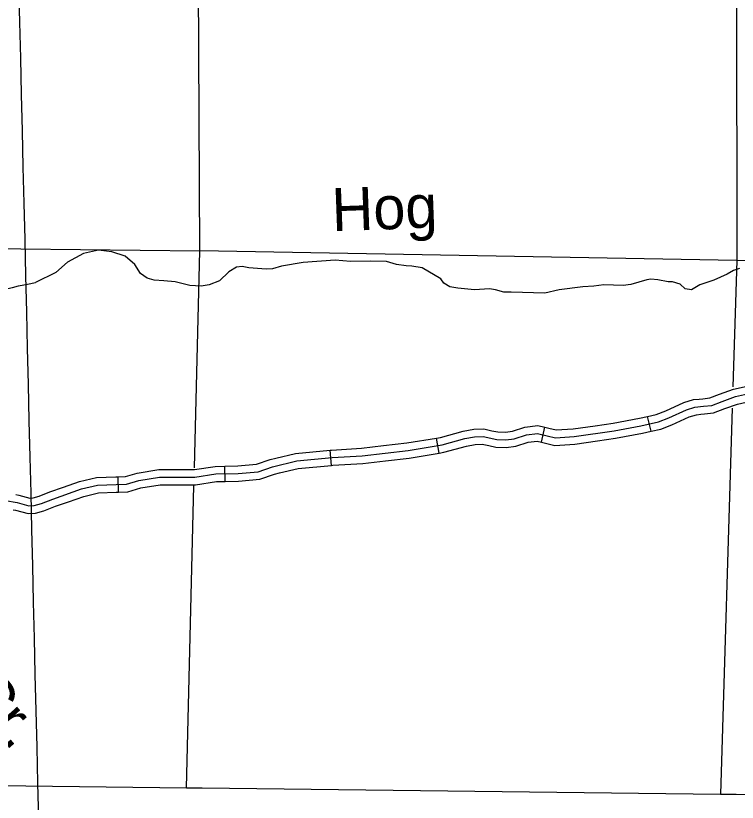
# Model space of a CAD drawing. Extents: x -19 to 366, y -4 to 359.
# Drawn here: x 135.055 to 136.395, y 192.02 to 193.481 of the extents above; entities that cross this region are included whole.
import ezdxf

# ---------------------------------------------------------------- set-up
doc = ezdxf.new("R2010")
doc.units = 0
for name, color, linetype in [('R_Alt Surface', 7, 'Continuous'), ('R_Axis Annot', 7, 'Continuous'), ('R_Temp Easement', 7, 'Continuous'), ('Sheet Fence', 7, 'Continuous'), ('T_Indications', 7, 'Continuous')]:
    doc.layers.add(name, color=color, linetype=linetype)

msp = doc.modelspace()

# ---------------------------------------------------------------- linework, layer by layer
at = {"layer": 'R_Alt Surface'}
msp.add_lwpolyline([(133.9509, 192.0638), (134.386, 192.0586), (134.4263, 192.0586), (135.372, 192.0471), (135.4008, 192.0467), (136.3634, 192.0352), (136.3927, 192.035), (137.3674, 192.0278), (137.3965, 192.0275), (137.874, 192.0242)], dxfattribs=at)
at = {"layer": 'R_Axis Annot'}
for points in [[(136.3928, 194.0289), (136.3939, 193.0262)], [(135.3964, 193.0443), (135.3933, 193.6647)], [(134.3989, 193.0554), (135.3964, 193.0443)], [(135.3865, 192.6409), (135.3964, 193.0443)], [(136.3939, 193.0262), (135.3964, 193.0443)], [(136.3939, 193.0262), (136.3867, 192.7915)], [(136.9875, 193.0242), (136.3939, 193.0262)], [(136.3855, 192.7522), (136.3634, 192.0352)], [(135.372, 192.0471), (135.3857, 192.6076)]]:
    msp.add_lwpolyline(points, dxfattribs=at)
at = {"layer": 'R_Temp Easement'}
for points in [[(135.475, 193.0154), (135.4649, 193.0139), (135.4502, 193.005), (135.4329, 192.9883), (135.4137, 192.9813), (135.399, 192.9787), (135.3779, 192.98), (135.351, 192.9864), (135.3299, 192.9883), (135.312, 192.9896), (135.2986, 192.9934), (135.2865, 193.0024), (135.2756, 193.019), (135.2577, 193.0344), (135.2334, 193.0421), (135.2084, 193.0453), (135.1803, 193.0395), (135.1509, 193.0229), (135.1291, 193.0037), (135.0916, 192.9857)], [(135.7798, 193.0162), (135.7616, 193.0191), (135.7434, 193.0244), (135.7139, 193.025), (135.6765, 193.0245), (135.6478, 193.027), (135.5884, 193.0226), (135.548, 193.016), (135.5314, 193.011), (135.5196, 193.0099), (135.4879, 193.0124), (135.475, 193.0154)], [(136.3991, 193.0117), (136.3878, 193.0075), (136.3761, 193.0006), (136.3512, 192.9895), (136.3252, 192.9811), (136.3097, 192.9719), (136.298, 192.9737), (136.2885, 192.9824), (136.2745, 192.9869), (136.2662, 192.9865), (136.2472, 192.9902), (136.2344, 192.9917), (136.2268, 192.9905), (136.197, 192.9817), (136.183, 192.9798), (136.1471, 192.9808), (136.1282, 192.9784), (136.1078, 192.9772), (136.0639, 192.9717), (136.0375, 192.9659), (135.9751, 192.9676), (135.9611, 192.9672), (135.9456, 192.9716), (135.9346, 192.9735), (135.907, 192.9715), (135.8756, 192.9748), (135.8608, 192.9774), (135.8499, 192.9842), (135.8441, 192.9925), (135.8097, 193.0129), (135.7904, 193.0158), (135.7798, 193.0162)], [(134.6272, 192.9315), (134.6473, 192.9359), (134.6638, 192.9337), (134.704, 192.933), (134.7174, 192.9356), (134.7392, 192.9407), (134.7654, 192.9445), (134.7967, 192.9474), (134.8163, 192.9498), (134.8416, 192.9522), (134.868, 192.9559), (134.8957, 192.9593), (134.9304, 192.9614), (134.9698, 192.9638), (134.9974, 192.9667), (135.0132, 192.9688), (135.0484, 192.976), (135.06, 192.9791), (135.0764, 192.9821), (135.0916, 192.9857)]]:
    msp.add_lwpolyline(points, dxfattribs=at)
at = {"layer": 'Sheet Fence'}
for points in [[(139.4406, 1.5315), (139.2511, 10.1473), (139.0608, 18.7633), (138.8699, 27.3793), (138.6784, 35.9956), (138.4861, 44.6119), (138.2932, 53.2285), (138.0997, 61.8451), (137.9055, 70.4619), (137.7106, 79.0789), (137.5151, 87.6959), (137.319, 96.3132), (137.1221, 104.9306), (136.9247, 113.5481), (136.7265, 122.1658), (136.5278, 130.7836), (136.3283, 139.4016), (136.1282, 148.0197), (135.9275, 156.6379), (135.7261, 165.2564), (135.5241, 173.8749), (135.3214, 182.4936), (135.1181, 191.1125), (134.9141, 199.7315), (134.7095, 208.3506), (134.5043, 216.9699), (134.2984, 225.5894), (134.0919, 234.209), (133.8847, 242.8288), (133.6769, 251.4487), (133.4685, 260.0687), (133.2594, 268.6889), (133.0497, 277.3093), (132.8393, 285.9298), (132.6283, 294.5504), (132.4167, 303.1713), (132.2044, 311.7922), (131.9916, 320.4133), (131.778, 329.0346), (131.5639, 337.656), (131.3491, 346.2776)], [(0, 189.5162), (7.1121, 189.5206), (14.2243, 189.5339), (21.3364, 189.556), (28.4484, 189.5869), (35.5605, 189.6267), (42.6725, 189.6754), (49.7844, 189.7329), (56.8962, 189.7992), (64.0079, 189.8744), (71.1196, 189.9584), (78.2311, 190.0512), (85.3425, 190.1529), (92.4538, 190.2635), (99.5649, 190.3829), (106.6759, 190.5111), (113.7867, 190.6482), (120.8974, 190.7941), (128.0078, 190.9489), (135.1181, 191.1125), (142.2282, 191.2849), (149.338, 191.4662), (156.4476, 191.6563), (163.5569, 191.8553), (170.666, 192.0631), (177.7749, 192.2798), (184.8835, 192.5053), (191.9917, 192.7396), (199.0997, 192.9828), (206.2074, 193.2348), (213.3147, 193.4956), (220.4218, 193.7653), (227.5285, 194.0438), (234.6348, 194.3312), (241.7408, 194.6274), (248.8464, 194.9324), (255.9516, 195.2463), (263.0564, 195.569), (270.1608, 195.9005), (277.2648, 196.2409), (284.3683, 196.5901), (291.4715, 196.9481), (298.5741, 197.315), (305.6763, 197.6907), (312.7781, 198.0753), (319.8793, 198.4686), (326.9801, 198.8708), (334.0804, 199.2818), (341.1801, 199.7017)]]:
    msp.add_spline(points, degree=3, dxfattribs=at)
at = {"layer": 'T_Indications'}
for p, q in [((136.2347, 192.709), (136.2283, 192.7367)), ((136.031, 192.6888), (136.0374, 192.7165)), ((135.8408, 192.6685), (135.8363, 192.6965)), ((135.6413, 192.6458), (135.6386, 192.674)), ((135.4435, 192.6159), (135.4429, 192.6443)), ((135.2455, 192.5961), (135.2449, 192.6245))]:
    msp.add_line(p, q, dxfattribs=at)
for points in [[(136.3242, 192.7689), (136.3308, 192.7696), (136.3439, 192.771), (136.3615, 192.778), (136.3875, 192.7871), (136.4188, 192.794)], [(136.3161, 192.7538), (136.3323, 192.7555), (136.3473, 192.7571), (136.3665, 192.7646), (136.3914, 192.7734), (136.4305, 192.7821)], [(136.2283, 192.7367), (136.2441, 192.7404), (136.2623, 192.7473), (136.2953, 192.7626), (136.3134, 192.7678), (136.3242, 192.7689)], [(136.3271, 192.7407), (136.3339, 192.7413), (136.3508, 192.7432), (136.3714, 192.7513), (136.3953, 192.7597), (136.425, 192.7663)], [(135.0359, 192.5802), (135.0576, 192.5765), (135.0792, 192.5706), (135.0892, 192.5711), (135.1025, 192.5748), (135.1233, 192.5831), (135.177, 192.6019), (135.2065, 192.6089), (135.2411, 192.6102), (135.2606, 192.6106), (135.2835, 192.6177), (135.3218, 192.6239), (135.3534, 192.6239), (135.3875, 192.6239), (135.4262, 192.6298), (135.4678, 192.6306), (135.5048, 192.6339), (135.5315, 192.6431), (135.5768, 192.6539), (135.6425, 192.6601), (135.6983, 192.6635), (135.7832, 192.6735), (135.8468, 192.6839), (135.8888, 192.6955), (135.9067, 192.6989), (135.9225, 192.6993), (135.9479, 192.6939), (135.965, 192.693), (135.9804, 192.6951), (136.0033, 192.7026), (136.0236, 192.7051), (136.0415, 192.7009), (136.0573, 192.6972), (136.0915, 192.6993), (136.1663, 192.7101), (136.2159, 192.7193), (136.2483, 192.7268), (136.2679, 192.7342), (136.3003, 192.7492), (136.3161, 192.7538)], [(136.2347, 192.709), (136.2525, 192.7131), (136.2734, 192.7211), (136.3053, 192.7359), (136.3188, 192.7398), (136.3271, 192.7407)], [(136.131, 192.7193), (136.164, 192.7241), (136.213, 192.7332), (136.2283, 192.7367)], [(135.8363, 192.6965), (135.8438, 192.6978), (135.8856, 192.7094), (135.9052, 192.713), (135.9239, 192.7135), (135.9392, 192.7102)], [(135.9392, 192.7102), (135.9498, 192.708), (135.9644, 192.7073), (135.9772, 192.709), (136.0001, 192.7165), (136.0244, 192.7195), (136.0374, 192.7165)], [(136.0374, 192.7165), (136.0448, 192.7148), (136.0586, 192.7115), (136.09, 192.7134), (136.131, 192.7193)], [(136.1351, 192.6912), (136.1686, 192.6961), (136.2187, 192.7053), (136.2347, 192.709)], [(135.6386, 192.674), (135.6414, 192.6743), (135.697, 192.6776), (135.7379, 192.6824)], [(135.7379, 192.6824), (135.7812, 192.6875), (135.8363, 192.6965)], [(135.8408, 192.6685), (135.8499, 192.67), (135.892, 192.6817), (135.9082, 192.6847), (135.9212, 192.685), (135.9333, 192.6825)], [(135.9333, 192.6825), (135.9461, 192.6797), (135.9656, 192.6788), (135.9836, 192.6812), (136.0064, 192.6887), (136.0229, 192.6907), (136.031, 192.6888)], [(136.031, 192.6888), (136.0383, 192.6871), (136.0561, 192.6829), (136.0929, 192.6851), (136.1351, 192.6912)], [(135.538, 192.6592), (135.5745, 192.6679), (135.6386, 192.674)], [(135.7412, 192.6542), (135.7851, 192.6594), (135.8408, 192.6685)], [(135.4429, 192.6443), (135.467, 192.6448), (135.5018, 192.6479), (135.5275, 192.6567), (135.538, 192.6592)], [(135.6413, 192.6458), (135.6436, 192.646), (135.6995, 192.6493), (135.7412, 192.6542)], [(135.3437, 192.6381), (135.3534, 192.6381), (135.3864, 192.6381), (135.425, 192.6439), (135.4429, 192.6443)], [(135.5446, 192.6316), (135.5791, 192.6399), (135.6413, 192.6458)], [(135.1432, 192.6051), (135.173, 192.6155), (135.2046, 192.6231), (135.2407, 192.6244), (135.2449, 192.6245)], [(135.2449, 192.6245), (135.2583, 192.6248), (135.2802, 192.6315), (135.3206, 192.6381), (135.3437, 192.6381)], [(135.4435, 192.6159), (135.4686, 192.6164), (135.5078, 192.6199), (135.5354, 192.6294), (135.5446, 192.6316)], [(135.2455, 192.5961), (135.2629, 192.5965), (135.2868, 192.6038), (135.3229, 192.6097), (135.3437, 192.6097)], [(135.3437, 192.6097), (135.3534, 192.6097), (135.3886, 192.6097), (135.4274, 192.6156), (135.4435, 192.6159)], [(135.0547, 192.5914), (135.0606, 192.5904), (135.0808, 192.5849), (135.087, 192.5852), (135.0979, 192.5883), (135.1183, 192.5964), (135.1432, 192.6051)], [(135.1525, 192.5783), (135.181, 192.5882), (135.2085, 192.5948), (135.2415, 192.596), (135.2455, 192.5961)], [(135.0498, 192.5634), (135.0545, 192.5626), (135.0776, 192.5564), (135.0915, 192.5569), (135.1071, 192.5613), (135.1283, 192.5698), (135.1525, 192.5783)]]:
    msp.add_lwpolyline(points, dxfattribs=at)

# ---------------------------------------------------------------- texts
at = {"layer": 'R_Temp Easement'}
for s, rotation, p in [('Hog', 2.0404, (135.6428, 193.0805)), ('Cr.', 311.0465, (134.9554, 192.2209))]:
    msp.add_text(s, height=0.08, rotation=rotation, dxfattribs=at).set_placement(p)

doc.saveas('drawing.dxf')
